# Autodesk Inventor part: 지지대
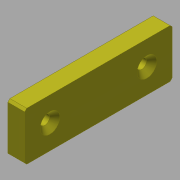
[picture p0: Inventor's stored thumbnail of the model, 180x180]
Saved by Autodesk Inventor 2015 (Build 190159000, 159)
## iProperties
Created: 2017-04
Part Number: 지지대
Material: 강철
Document SubType Name: Modeling
Designer: mduedu
Density: 7.85 g/cm^3
Appearance: 밝은 황색
Mass: 98.0769 g
Surface Area: 48.2288 cm^2
Volume: 12.4939 cm^3
Author: mduedu
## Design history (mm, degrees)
sketch "스케치1"
  geometry: L1 (23, -35)-(23, 35); L2 (0, -35)-(0, 35); L3 (0, 35)-(23, 35); L4 (0, -35)-(23, -35); 2 further points
  constraints: 8 end point, 2 parallel, 1 coincident, 1 midpoint, 1 perpendicular, 1 vertical
  dimensions: "d1" = 23 distance between parallel lines of L2 L1; "d15" = 70 distance of L1.start L1.end
extrude "돌출1" new body sketch "스케치1" distance "d2" = 8; taper "d3" = 0 deg
chamfer "모따기2" distance "d16" = 1; stored, may be unused: second distance "d17" = 2, angle "d18" = 45 deg
sketch "스케치2"
  geometry: L1 (1, -35)-(22, -35) reference; L2 (23, -34)-(23, 34) reference; L3 (22, 35)-(1, 35) reference; L4 (0, 34)-(0, -34) reference; L5 (11.5, 35)-(11.5, -35); L6 (23, 0)-(0, 0); L7 (1, -35)-(0, -34) reference; L8 (23, -34)-(22, -35) reference; L9 (22, 35)-(23, 34) reference; L10 (0, 34)-(1, 35) reference; 2 further points
  constraints: 4 end point, 4 midpoint, 1 point on line, 1 symmetric about line
  dimensions: "d7" = 12 distance from line of point (11.5, 23) L3
  node "투영된 루프1"
sketch "스케치3"
  geometry: 4 further points
  constraints: 2 coincident
hole "구멍1" sketch "스케치3" at (11.5, 23), (11.5, -23) diameter "d8" = 4.5; stored, may be unused: countersink angle "d12" = 90 deg, drill point angle "d14" = 0 deg; dims "d9" = 6, "d10" = 9.4, "d11" = 2, "d13" = 8
node "솔리드2"
node "솔리드1"
